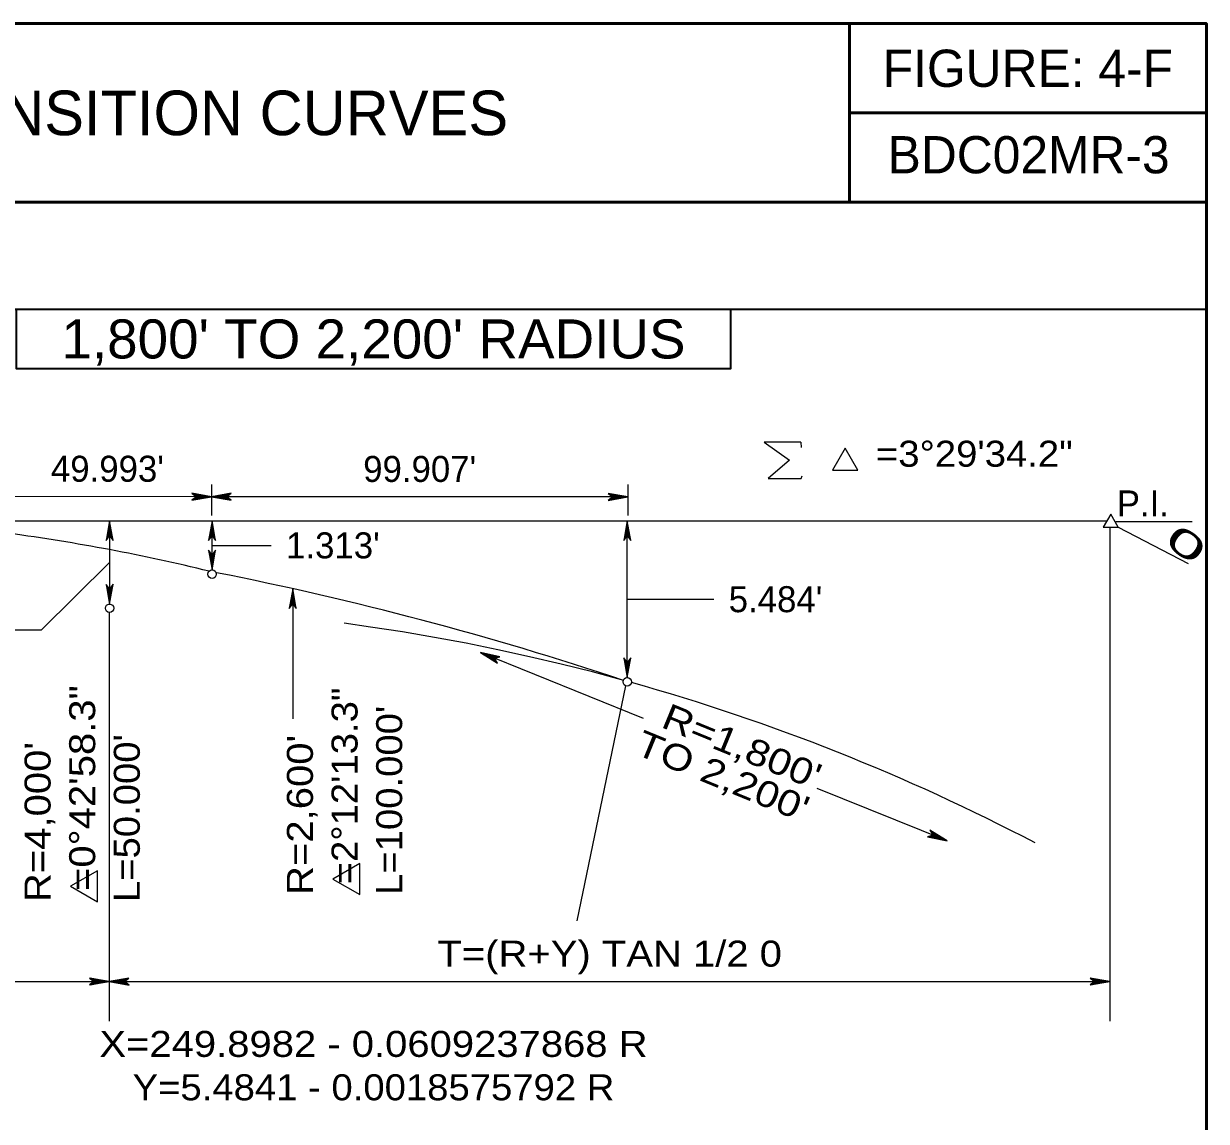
# Model space of a CAD drawing. Extents: x -1.327 to -0.652, y 2.966 to 3.85.
# Drawn here: x -1.1033 to -0.6892, y 3.4214 to 3.8059 of the extents above; entities that cross this region are included whole.
import ezdxf
from ezdxf.enums import TextEntityAlignment as Align

# ---------------------------------------------------------------- set-up
doc = ezdxf.new("R2010")
doc.units = 0
doc.header["$LTSCALE"] = 0.0036
doc.linetypes.add('LONG_DASHED', pattern=[7.5, 6, -1.5])
doc.layers.add('1', color=7, linetype='Continuous', lineweight=25)
doc.layers.add('24', color=7, linetype='Continuous', lineweight=25)

msp = doc.modelspace()

# ---------------------------------------------------------------- linework, layer by layer
at = {"layer": '1', "lineweight": 53}
for p, q in [((-0.814158, 3.805875), (-0.814158, 3.743375)), ((-0.814158, 3.774625), (-0.689158, 3.774625)), ((-1.272492, 3.743375), (-0.689158, 3.743375))]:
    msp.add_line(p, q, dxfattribs=at)
at = {"layer": '1', "lineweight": 35}
msp.add_line((-1.272492, 3.705875), (-0.689158, 3.705875), dxfattribs=at)
at = {"layer": '1'}
for p, q in [((-0.831217, 3.659283), (-0.830992, 3.657433)), ((-0.830992, 3.646533), (-0.83075, 3.647458)), ((-1.254817, 3.631783), (-0.723983, 3.631783)), ((-0.72295, 3.629483), (-0.72295, 3.456567)), ((-0.720858, 3.6315), (-0.694117, 3.6315)), ((-0.719983, 3.629483), (-0.695475, 3.616758)), ((-1.073342, 3.599592), (-1.073342, 3.456567)), ((-0.892517, 3.574025), (-0.909575, 3.4917))]:
    msp.add_line(p, q, dxfattribs=at)
at = {"layer": '1', "lineweight": 13}
for p, q in [((-1.037542, 3.644467), (-1.037533, 3.633567)), ((-0.891725, 3.644508), (-0.891717, 3.633658)), ((-1.037542, 3.640217), (-1.110442, 3.64025)), ((-0.891717, 3.640125), (-1.037542, 3.640208)), ((-1.073233, 3.631783), (-1.073233, 3.602617)), ((-1.03735, 3.614542), (-1.03735, 3.631783)), ((-0.891942, 3.576842), (-0.891942, 3.631783)), ((-1.03735, 3.623167), (-1.016642, 3.623167)), ((-1.0091, 3.607983), (-1.0091, 3.562358)), ((-0.891942, 3.604317), (-0.861642, 3.604317)), ((-0.886242, 3.56255), (-0.943383, 3.585617)), ((-0.779975, 3.51965), (-0.825492, 3.538025))]:
    msp.add_line(p, q, dxfattribs=at)
at = {"layer": '1', "linetype": 'LONG_DASHED'}
msp.add_line((-1.256283, 3.60115), (-1.074725, 3.60115), dxfattribs=at)
at = {"layer": '1', "lineweight": 53}
msp.add_lwpolyline([(-1.272492, 3.805875), (-0.689158, 3.805875), (-0.689158, 3.014208), (-1.272492, 3.014208)], close=True, dxfattribs=at)
at = {"layer": '1', "lineweight": 35}
msp.add_lwpolyline([(-0.855825, 3.705875), (-0.855825, 3.685042), (-1.105825, 3.685042), (-1.105825, 3.705875)], dxfattribs=at)
at = {"layer": '1'}
msp.add_lwpolyline([(-0.831217, 3.659283), (-0.843958, 3.659283), (-0.835158, 3.653025), (-0.842575, 3.646533), (-0.830992, 3.646533)], dxfattribs=at)
for points in [[(-0.815617, 3.65715), (-0.820025, 3.649517), (-0.811217, 3.649517)], [(-0.725308, 3.629483), (-0.719983, 3.629483), (-0.72265, 3.634092)], [(-1.086883, 3.503792), (-1.0775, 3.498375), (-1.0775, 3.509208)], [(-0.995008, 3.506292), (-0.985625, 3.500875), (-0.985625, 3.511708)]]:
    msp.add_lwpolyline(points, close=True, dxfattribs=at)
at = {"layer": '1', "lineweight": 13}
for points in [[(-1.073233, 3.6172), (-1.0972, 3.593508), (-1.114867, 3.593508)], [(-1.256283, 3.470417), (-1.073342, 3.470417), (-0.72295, 3.470417)]]:
    msp.add_lwpolyline(points, dxfattribs=at)
at = {"layer": '1'}
for centre in [(-1.037348, 3.613073), (-1.073254, 3.601146), (-0.891942, 3.575375)]:
    msp.add_circle(centre, 0.001471, dxfattribs=at)
for centre, radius, start, end in [((-1.197416, 2.964184), 0.669103, 76.25089, 82.35755), ((-1.259535, 2.479835), 1.15561, 71.52306, 78.8348), ((-1.08784, 2.872506), 0.72981, 62.34623, 74.31303)]:
    msp.add_arc(centre, radius, start, end, dxfattribs=at)
at = {"layer": '1', "linetype": 'LONG_DASHED'}
msp.add_arc((-1.08784, 2.872506), 0.72981, 74.53069, 88.76241, dxfattribs=at)
at = {"layer": '24'}
for points in [[(-1.037542, 3.640217), (-1.044475, 3.641442), (-1.042817, 3.640217), (-1.044433, 3.639017), (-1.037542, 3.640217), (-1.038, 3.640208), (-1.044275, 3.64135), (-1.042683, 3.6402), (-1.044158, 3.639108), (-1.03825, 3.640183), (-1.038483, 3.640217), (-1.043858, 3.641175), (-1.04265, 3.640208), (-1.043892, 3.639267), (-1.038583, 3.640217), (-1.038817, 3.640183), (-1.043517, 3.641033), (-1.0426, 3.640217), (-1.043533, 3.639375), (-1.039483, 3.640183), (-1.039875, 3.640183), (-1.043167, 3.640858), (-1.042525, 3.640242), (-1.043217, 3.63955), (-1.03995, 3.640217), (-1.040317, 3.640242), (-1.042792, 3.640667), (-1.042317, 3.640183), (-1.042833, 3.639708), (-1.040658, 3.640217), (-1.041008, 3.64025), (-1.042492, 3.640542), (-1.04225, 3.6402), (-1.04265, 3.639833), (-1.041183, 3.640217), (-1.042158, 3.64045), (-1.042017, 3.640183), (-1.042442, 3.639917), (-1.041433, 3.640183), (-1.042067, 3.640342), (-1.0418, 3.640133), (-1.042108, 3.640008), (-1.0418, 3.6402), (-1.041958, 3.640242)], [(-1.037542, 3.640208), (-1.030608, 3.638983), (-1.032267, 3.640208), (-1.03065, 3.641408), (-1.037542, 3.640208), (-1.037083, 3.640217), (-1.030808, 3.639067), (-1.0324, 3.640217), (-1.030925, 3.641317), (-1.036833, 3.640242), (-1.0366, 3.640208), (-1.031225, 3.63925), (-1.032433, 3.640217), (-1.031192, 3.641158), (-1.0365, 3.640208), (-1.036267, 3.640242), (-1.031567, 3.639392), (-1.032483, 3.640208), (-1.03155, 3.64105), (-1.0356, 3.640242), (-1.035208, 3.640242), (-1.031917, 3.639567), (-1.032558, 3.640183), (-1.031867, 3.640875), (-1.035133, 3.640208), (-1.034767, 3.640183), (-1.032292, 3.639758), (-1.032767, 3.640242), (-1.03225, 3.640717), (-1.034425, 3.640208), (-1.034075, 3.640175), (-1.032592, 3.639883), (-1.032833, 3.640217), (-1.032433, 3.640592), (-1.0339, 3.640208), (-1.032925, 3.639975), (-1.033067, 3.640242), (-1.032642, 3.640508), (-1.03365, 3.640242), (-1.033017, 3.640083), (-1.033283, 3.640292), (-1.032975, 3.640417), (-1.033283, 3.640225), (-1.033125, 3.640183)], [(-0.891717, 3.640125), (-0.89865, 3.64135), (-0.896992, 3.640125), (-0.898608, 3.638925), (-0.891717, 3.640125), (-0.892175, 3.640117), (-0.89845, 3.641267), (-0.896858, 3.640117), (-0.898333, 3.639017), (-0.892425, 3.640092), (-0.892658, 3.640125), (-0.898033, 3.641083), (-0.896825, 3.640117), (-0.898067, 3.639175), (-0.892758, 3.640125), (-0.892992, 3.640092), (-0.897692, 3.640942), (-0.896775, 3.640125), (-0.897708, 3.639283), (-0.893658, 3.640092), (-0.89405, 3.640092), (-0.897342, 3.640767), (-0.8967, 3.64015), (-0.897392, 3.639458), (-0.894125, 3.640125), (-0.894492, 3.64015), (-0.896967, 3.640575), (-0.896492, 3.640092), (-0.897008, 3.639617), (-0.894833, 3.640125), (-0.895183, 3.640158), (-0.896667, 3.64045), (-0.896425, 3.640117), (-0.896825, 3.639742), (-0.895358, 3.640125), (-0.896333, 3.640358), (-0.896192, 3.640092), (-0.896617, 3.639825), (-0.895608, 3.640092), (-0.896242, 3.64025), (-0.895975, 3.640042), (-0.896283, 3.639917), (-0.895975, 3.640108), (-0.896133, 3.64015)], [(-1.073233, 3.631783), (-1.074458, 3.62485), (-1.073233, 3.626508), (-1.072025, 3.624892), (-1.073233, 3.631783), (-1.073225, 3.631325), (-1.074367, 3.62505), (-1.073217, 3.626642), (-1.072125, 3.625167), (-1.0732, 3.631075), (-1.073233, 3.630842), (-1.074192, 3.625467), (-1.073217, 3.626675), (-1.072275, 3.625433), (-1.073233, 3.630742), (-1.0732, 3.630508), (-1.07405, 3.625808), (-1.073233, 3.626725), (-1.072392, 3.625792), (-1.0732, 3.629842), (-1.0732, 3.62945), (-1.073875, 3.626158), (-1.07325, 3.6268), (-1.072567, 3.626108), (-1.073233, 3.629375), (-1.073258, 3.629008), (-1.073675, 3.626533), (-1.0732, 3.627008), (-1.072725, 3.626492), (-1.073233, 3.628667), (-1.073267, 3.628317), (-1.07355, 3.626833), (-1.073217, 3.627075), (-1.07285, 3.626675), (-1.073233, 3.628142), (-1.073467, 3.627167), (-1.0732, 3.627308), (-1.072933, 3.626883), (-1.0732, 3.627892), (-1.073358, 3.627258), (-1.07315, 3.627525), (-1.073025, 3.627217), (-1.073217, 3.627525), (-1.07325, 3.627367)], [(-1.03735, 3.631783), (-1.038575, 3.62485), (-1.03735, 3.626508), (-1.036142, 3.624892), (-1.03735, 3.631783), (-1.037342, 3.631325), (-1.038483, 3.62505), (-1.037333, 3.626642), (-1.036242, 3.625167), (-1.037317, 3.631075), (-1.03735, 3.630842), (-1.038308, 3.625467), (-1.037333, 3.626675), (-1.036392, 3.625433), (-1.03735, 3.630742), (-1.037317, 3.630508), (-1.038167, 3.625808), (-1.03735, 3.626725), (-1.036508, 3.625792), (-1.037317, 3.629842), (-1.037317, 3.62945), (-1.037992, 3.626158), (-1.037367, 3.6268), (-1.036683, 3.626108), (-1.03735, 3.629375), (-1.037375, 3.629008), (-1.037792, 3.626533), (-1.037317, 3.627008), (-1.036842, 3.626492), (-1.03735, 3.628667), (-1.037383, 3.628317), (-1.037667, 3.626833), (-1.037333, 3.627075), (-1.036967, 3.626675), (-1.03735, 3.628142), (-1.037583, 3.627167), (-1.037317, 3.627308), (-1.03705, 3.626883), (-1.037317, 3.627892), (-1.037475, 3.627258), (-1.037267, 3.627525), (-1.037142, 3.627217), (-1.037333, 3.627525), (-1.037367, 3.627367)], [(-0.891942, 3.631783), (-0.893167, 3.62485), (-0.891942, 3.626508), (-0.890733, 3.624892), (-0.891942, 3.631783), (-0.891933, 3.631325), (-0.893075, 3.62505), (-0.891925, 3.626642), (-0.890833, 3.625167), (-0.891908, 3.631075), (-0.891942, 3.630842), (-0.8929, 3.625467), (-0.891925, 3.626675), (-0.890983, 3.625433), (-0.891942, 3.630742), (-0.891908, 3.630508), (-0.892758, 3.625808), (-0.891942, 3.626725), (-0.8911, 3.625792), (-0.891908, 3.629842), (-0.891908, 3.62945), (-0.892583, 3.626158), (-0.891958, 3.6268), (-0.891275, 3.626108), (-0.891942, 3.629375), (-0.891967, 3.629008), (-0.892383, 3.626533), (-0.891908, 3.627008), (-0.891433, 3.626492), (-0.891942, 3.628667), (-0.891975, 3.628317), (-0.892258, 3.626833), (-0.891925, 3.627075), (-0.891558, 3.626675), (-0.891942, 3.628142), (-0.892175, 3.627167), (-0.891908, 3.627308), (-0.891642, 3.626883), (-0.891908, 3.627892), (-0.892067, 3.627258), (-0.891858, 3.627525), (-0.891733, 3.627217), (-0.891925, 3.627525), (-0.891958, 3.627367)], [(-1.03735, 3.614542), (-1.036125, 3.621475), (-1.03735, 3.619817), (-1.038558, 3.621433), (-1.03735, 3.614542), (-1.037367, 3.615), (-1.036217, 3.621275), (-1.037367, 3.619683), (-1.038458, 3.621158), (-1.037383, 3.61525), (-1.03735, 3.615483), (-1.036392, 3.620858), (-1.037367, 3.61965), (-1.038308, 3.620892), (-1.03735, 3.615583), (-1.037383, 3.615817), (-1.036533, 3.620517), (-1.03735, 3.6196), (-1.038192, 3.620533), (-1.037383, 3.616483), (-1.037383, 3.616875), (-1.036708, 3.620167), (-1.037333, 3.619525), (-1.038017, 3.620217), (-1.03735, 3.61695), (-1.037325, 3.617317), (-1.036908, 3.619792), (-1.037383, 3.619317), (-1.037858, 3.619833), (-1.03735, 3.617658), (-1.037317, 3.618008), (-1.037033, 3.619492), (-1.037367, 3.61925), (-1.037733, 3.61965), (-1.03735, 3.618183), (-1.037117, 3.619158), (-1.037383, 3.619017), (-1.03765, 3.619442), (-1.037383, 3.618433), (-1.037225, 3.619067), (-1.037433, 3.6188), (-1.037558, 3.619108), (-1.037367, 3.6188), (-1.037333, 3.618958)], [(-1.073233, 3.602617), (-1.072008, 3.60955), (-1.073233, 3.607892), (-1.074442, 3.609508), (-1.073233, 3.602617), (-1.07325, 3.603075), (-1.0721, 3.60935), (-1.07325, 3.607758), (-1.074342, 3.609233), (-1.073267, 3.603325), (-1.073233, 3.603558), (-1.072275, 3.608933), (-1.07325, 3.607725), (-1.074192, 3.608967), (-1.073233, 3.603658), (-1.073267, 3.603892), (-1.072417, 3.608592), (-1.073233, 3.607675), (-1.074075, 3.608608), (-1.073267, 3.604558), (-1.073267, 3.60495), (-1.072592, 3.608242), (-1.073217, 3.6076), (-1.0739, 3.608292), (-1.073233, 3.605025), (-1.073208, 3.605392), (-1.072792, 3.607867), (-1.073267, 3.607392), (-1.073742, 3.607908), (-1.073233, 3.605733), (-1.0732, 3.606083), (-1.072917, 3.607567), (-1.07325, 3.607325), (-1.073617, 3.607725), (-1.073233, 3.606258), (-1.073, 3.607233), (-1.073267, 3.607092), (-1.073533, 3.607517), (-1.073267, 3.606508), (-1.073108, 3.607142), (-1.073317, 3.606875), (-1.073442, 3.607183), (-1.07325, 3.606875), (-1.073217, 3.607033)], [(-1.0091, 3.607983), (-1.010325, 3.60105), (-1.0091, 3.602708), (-1.007892, 3.601092), (-1.0091, 3.607983), (-1.009092, 3.607525), (-1.010233, 3.60125), (-1.009083, 3.602842), (-1.007992, 3.601367), (-1.009067, 3.607275), (-1.0091, 3.607042), (-1.010058, 3.601667), (-1.009083, 3.602875), (-1.008142, 3.601633), (-1.0091, 3.606942), (-1.009067, 3.606708), (-1.009917, 3.602008), (-1.0091, 3.602925), (-1.008258, 3.601992), (-1.009067, 3.606042), (-1.009067, 3.60565), (-1.009742, 3.602358), (-1.009117, 3.603), (-1.008433, 3.602308), (-1.0091, 3.605575), (-1.009125, 3.605208), (-1.009542, 3.602733), (-1.009067, 3.603208), (-1.008592, 3.602692), (-1.0091, 3.604867), (-1.009133, 3.604517), (-1.009417, 3.603033), (-1.009083, 3.603275), (-1.008717, 3.602875), (-1.0091, 3.604342), (-1.009333, 3.603367), (-1.009067, 3.603508), (-1.0088, 3.603083), (-1.009067, 3.604092), (-1.009225, 3.603458), (-1.009017, 3.603725), (-1.008892, 3.603417), (-1.009083, 3.603725), (-1.009117, 3.603567)], [(-0.943383, 3.585617), (-0.937417, 3.581883), (-0.938492, 3.583642), (-0.936542, 3.58415), (-0.943383, 3.585617), (-0.94295, 3.585458), (-0.937558, 3.582042), (-0.938608, 3.583708), (-0.936833, 3.584167), (-0.942717, 3.585383), (-0.942508, 3.585267), (-0.937883, 3.582367), (-0.938642, 3.583717), (-0.937142, 3.584125), (-0.942417, 3.585225), (-0.942192, 3.585175), (-0.93815, 3.582625), (-0.938692, 3.583725), (-0.937508, 3.584158), (-0.941567, 3.584925), (-0.941208, 3.584775), (-0.938408, 3.582917), (-0.938767, 3.583733), (-0.937867, 3.584117), (-0.94115, 3.584717), (-0.940817, 3.584558), (-0.938683, 3.583242), (-0.938942, 3.583858), (-0.938292, 3.584108), (-0.940492, 3.58445), (-0.940183, 3.584283), (-0.938917, 3.583467), (-0.939017, 3.583867), (-0.9385, 3.584058), (-0.94, 3.58425), (-0.939192, 3.583675), (-0.939225, 3.583975), (-0.938725, 3.584058), (-0.939767, 3.584192), (-0.939233, 3.583808), (-0.9394, 3.5841), (-0.939075, 3.5841), (-0.939425, 3.584033), (-0.939292, 3.583942)], [(-0.891942, 3.576842), (-0.890717, 3.583775), (-0.891942, 3.582117), (-0.89315, 3.583733), (-0.891942, 3.576842), (-0.891958, 3.5773), (-0.890808, 3.583575), (-0.891958, 3.581983), (-0.89305, 3.583458), (-0.891975, 3.57755), (-0.891942, 3.577783), (-0.890983, 3.583158), (-0.891958, 3.58195), (-0.8929, 3.583192), (-0.891942, 3.577883), (-0.891975, 3.578117), (-0.891125, 3.582817), (-0.891942, 3.5819), (-0.892783, 3.582833), (-0.891975, 3.578783), (-0.891975, 3.579175), (-0.8913, 3.582467), (-0.891925, 3.581825), (-0.892608, 3.582517), (-0.891942, 3.57925), (-0.891917, 3.579617), (-0.8915, 3.582092), (-0.891975, 3.581617), (-0.89245, 3.582133), (-0.891942, 3.579958), (-0.891908, 3.580308), (-0.891625, 3.581792), (-0.891958, 3.58155), (-0.892325, 3.58195), (-0.891942, 3.580483), (-0.891708, 3.581458), (-0.891975, 3.581317), (-0.892242, 3.581742), (-0.891975, 3.580733), (-0.891817, 3.581367), (-0.892025, 3.5811), (-0.89215, 3.581408), (-0.891958, 3.5811), (-0.891925, 3.581258)], [(-0.779975, 3.51965), (-0.785942, 3.523383), (-0.784867, 3.521625), (-0.786817, 3.521117), (-0.779975, 3.51965), (-0.780408, 3.519808), (-0.7858, 3.523225), (-0.78475, 3.521558), (-0.786525, 3.5211), (-0.780642, 3.519883), (-0.78085, 3.52), (-0.785475, 3.5229), (-0.784717, 3.52155), (-0.786217, 3.521142), (-0.780942, 3.520042), (-0.781167, 3.520092), (-0.785208, 3.522642), (-0.784667, 3.521542), (-0.78585, 3.521108), (-0.781792, 3.520342), (-0.78215, 3.520492), (-0.78495, 3.52235), (-0.784592, 3.521533), (-0.785492, 3.52115), (-0.782208, 3.52055), (-0.782542, 3.520708), (-0.784675, 3.522025), (-0.784417, 3.521408), (-0.785067, 3.521158), (-0.782867, 3.520817), (-0.783175, 3.520983), (-0.784442, 3.5218), (-0.784342, 3.5214), (-0.784858, 3.521208), (-0.783358, 3.521017), (-0.784167, 3.521592), (-0.784133, 3.521292), (-0.784633, 3.521208), (-0.783592, 3.521075), (-0.784125, 3.521458), (-0.783958, 3.521167), (-0.784283, 3.521167), (-0.783933, 3.521233), (-0.784067, 3.521325)], [(-1.073342, 3.470417), (-1.080275, 3.471642), (-1.078617, 3.470417), (-1.080233, 3.469208), (-1.073342, 3.470417), (-1.0738, 3.470408), (-1.080075, 3.47155), (-1.078483, 3.4704), (-1.079958, 3.469308), (-1.07405, 3.470383), (-1.074283, 3.470417), (-1.079658, 3.471375), (-1.07845, 3.4704), (-1.079692, 3.469458), (-1.074383, 3.470417), (-1.074617, 3.470383), (-1.079317, 3.471233), (-1.0784, 3.470417), (-1.079333, 3.469575), (-1.075283, 3.470383), (-1.075675, 3.470383), (-1.078967, 3.471058), (-1.078325, 3.470433), (-1.079017, 3.46975), (-1.07575, 3.470417), (-1.076117, 3.470442), (-1.078592, 3.470858), (-1.078117, 3.470383), (-1.078633, 3.469908), (-1.076458, 3.470417), (-1.076808, 3.47045), (-1.078292, 3.470733), (-1.07805, 3.4704), (-1.07845, 3.470033), (-1.076983, 3.470417), (-1.077958, 3.47065), (-1.077817, 3.470383), (-1.078242, 3.470117), (-1.077233, 3.470383), (-1.077867, 3.470542), (-1.0776, 3.470333), (-1.077908, 3.470208), (-1.0776, 3.4704), (-1.077758, 3.470433)], [(-1.073342, 3.470417), (-1.066408, 3.469192), (-1.068067, 3.470417), (-1.06645, 3.471625), (-1.073342, 3.470417), (-1.072883, 3.470433), (-1.066608, 3.469283), (-1.0682, 3.470433), (-1.066725, 3.471525), (-1.072633, 3.47045), (-1.0724, 3.470417), (-1.067025, 3.469458), (-1.068233, 3.470433), (-1.066992, 3.471375), (-1.0723, 3.470417), (-1.072067, 3.47045), (-1.067367, 3.4696), (-1.068283, 3.470417), (-1.06735, 3.471258), (-1.0714, 3.47045), (-1.071008, 3.47045), (-1.067717, 3.469775), (-1.068358, 3.4704), (-1.067667, 3.471083), (-1.070933, 3.470417), (-1.070567, 3.470392), (-1.068092, 3.469975), (-1.068567, 3.47045), (-1.06805, 3.470925), (-1.070225, 3.470417), (-1.069875, 3.470383), (-1.068392, 3.4701), (-1.068633, 3.470433), (-1.068233, 3.4708), (-1.0697, 3.470417), (-1.068725, 3.470183), (-1.068867, 3.47045), (-1.068442, 3.470717), (-1.06945, 3.47045), (-1.068817, 3.470292), (-1.069083, 3.4705), (-1.068775, 3.470625), (-1.069083, 3.470433), (-1.068925, 3.4704)], [(-0.72295, 3.470417), (-0.729883, 3.471642), (-0.728225, 3.470417), (-0.729842, 3.469208), (-0.72295, 3.470417), (-0.723408, 3.470408), (-0.729683, 3.47155), (-0.728092, 3.4704), (-0.729567, 3.469308), (-0.723658, 3.470383), (-0.723892, 3.470417), (-0.729267, 3.471375), (-0.728058, 3.4704), (-0.7293, 3.469458), (-0.723992, 3.470417), (-0.724225, 3.470383), (-0.728925, 3.471233), (-0.728008, 3.470417), (-0.728942, 3.469575), (-0.724892, 3.470383), (-0.725283, 3.470383), (-0.728575, 3.471058), (-0.727933, 3.470433), (-0.728625, 3.46975), (-0.725358, 3.470417), (-0.725725, 3.470442), (-0.7282, 3.470858), (-0.727725, 3.470383), (-0.728242, 3.469908), (-0.726067, 3.470417), (-0.726417, 3.47045), (-0.7279, 3.470733), (-0.727658, 3.4704), (-0.728058, 3.470033), (-0.726592, 3.470417), (-0.727567, 3.47065), (-0.727425, 3.470383), (-0.72785, 3.470117), (-0.726842, 3.470383), (-0.727475, 3.470542), (-0.727208, 3.470333), (-0.727517, 3.470208), (-0.727208, 3.4704), (-0.727367, 3.470433)]]:
    msp.add_lwpolyline(points, dxfattribs=at)

# ---------------------------------------------------------------- texts
at = {"layer": '1'}
for s, height, p in [('FIGURE: 4-F', 0.01303, (-0.751663, 3.783733)), ('TRANSITION CURVES', 0.01562, (-1.043325, 3.766808)), ('BDC02MR-3', 0.01303, (-0.751379, 3.753458)), ("49.993'", 0.009108, (-1.073996, 3.645442)), ("99.907'", 0.009108, (-0.964638, 3.645375)), ('P.I.', 0.009108, (-0.711383, 3.633283))]:
    msp.add_text(s, height=height, dxfattribs=at).set_placement(p, align=Align.CENTER)
for s, height, width, p in [("1,800' TO 2,200' RADIUS", 0.01367, 1.05, (-0.980829, 3.688625)), ('=3°29\'34.2"', 0.009108, 1.1, (-0.770404, 3.650708)), ('T=(R+Y) TAN 1/2 0', 0.009108, 1.15, (-0.898108, 3.475625)), ('X=249.8982 - 0.0609237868 R', 0.009108, 1.15, (-0.980825, 3.444017)), ('Y=5.4841 - 0.0018575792 R', 0.009108, 1.1, (-0.980825, 3.428817))]:
    msp.add_text(s, height=height, dxfattribs=dict(at, width=width)).set_placement(p, align=Align.CENTER)
for s, rotation, width, p in [('0', 324.261, 2, (-0.698893, 3.61988)), ("R=1,800'", 337.75, 1.2, (-0.853483, 3.548571)), ("TO 2,200'", 337.75, 1.2, (-0.860199, 3.538195))]:
    msp.add_text(s, height=0.009108, rotation=rotation, dxfattribs=dict(at, width=width)).set_placement(p, align=Align.CENTER)
for s, p in [("1.313'", (-1.011433, 3.618608)), ("5.484'", (-0.856433, 3.599758))]:
    msp.add_text(s, height=0.009108, dxfattribs=at).set_placement(p)
for s, height, width, p in [(' =0°42\'58.3"', 0.009108, 1.15, (-1.078275, 3.498233)), (' =2°12\'13.3"', 0.009108, 1.1, (-0.9864, 3.500733)), ("L=100.000'", 0.009108, 1.1, (-0.970775, 3.500733)), ("R=4,000'", 0.009117, 1.15, (-1.0939, 3.498233)), ("L=50.000'", 0.009108, 1.1, (-1.06265, 3.498233)), ("R=2,600'", 0.009117, 1.15, (-1.002025, 3.500733))]:
    msp.add_text(s, height=height, rotation=90, dxfattribs=dict(at, width=width)).set_placement(p)

doc.saveas('drawing.dxf')
